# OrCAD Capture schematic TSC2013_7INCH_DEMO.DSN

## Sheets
1 BlockDiagram: size A3; rev: B
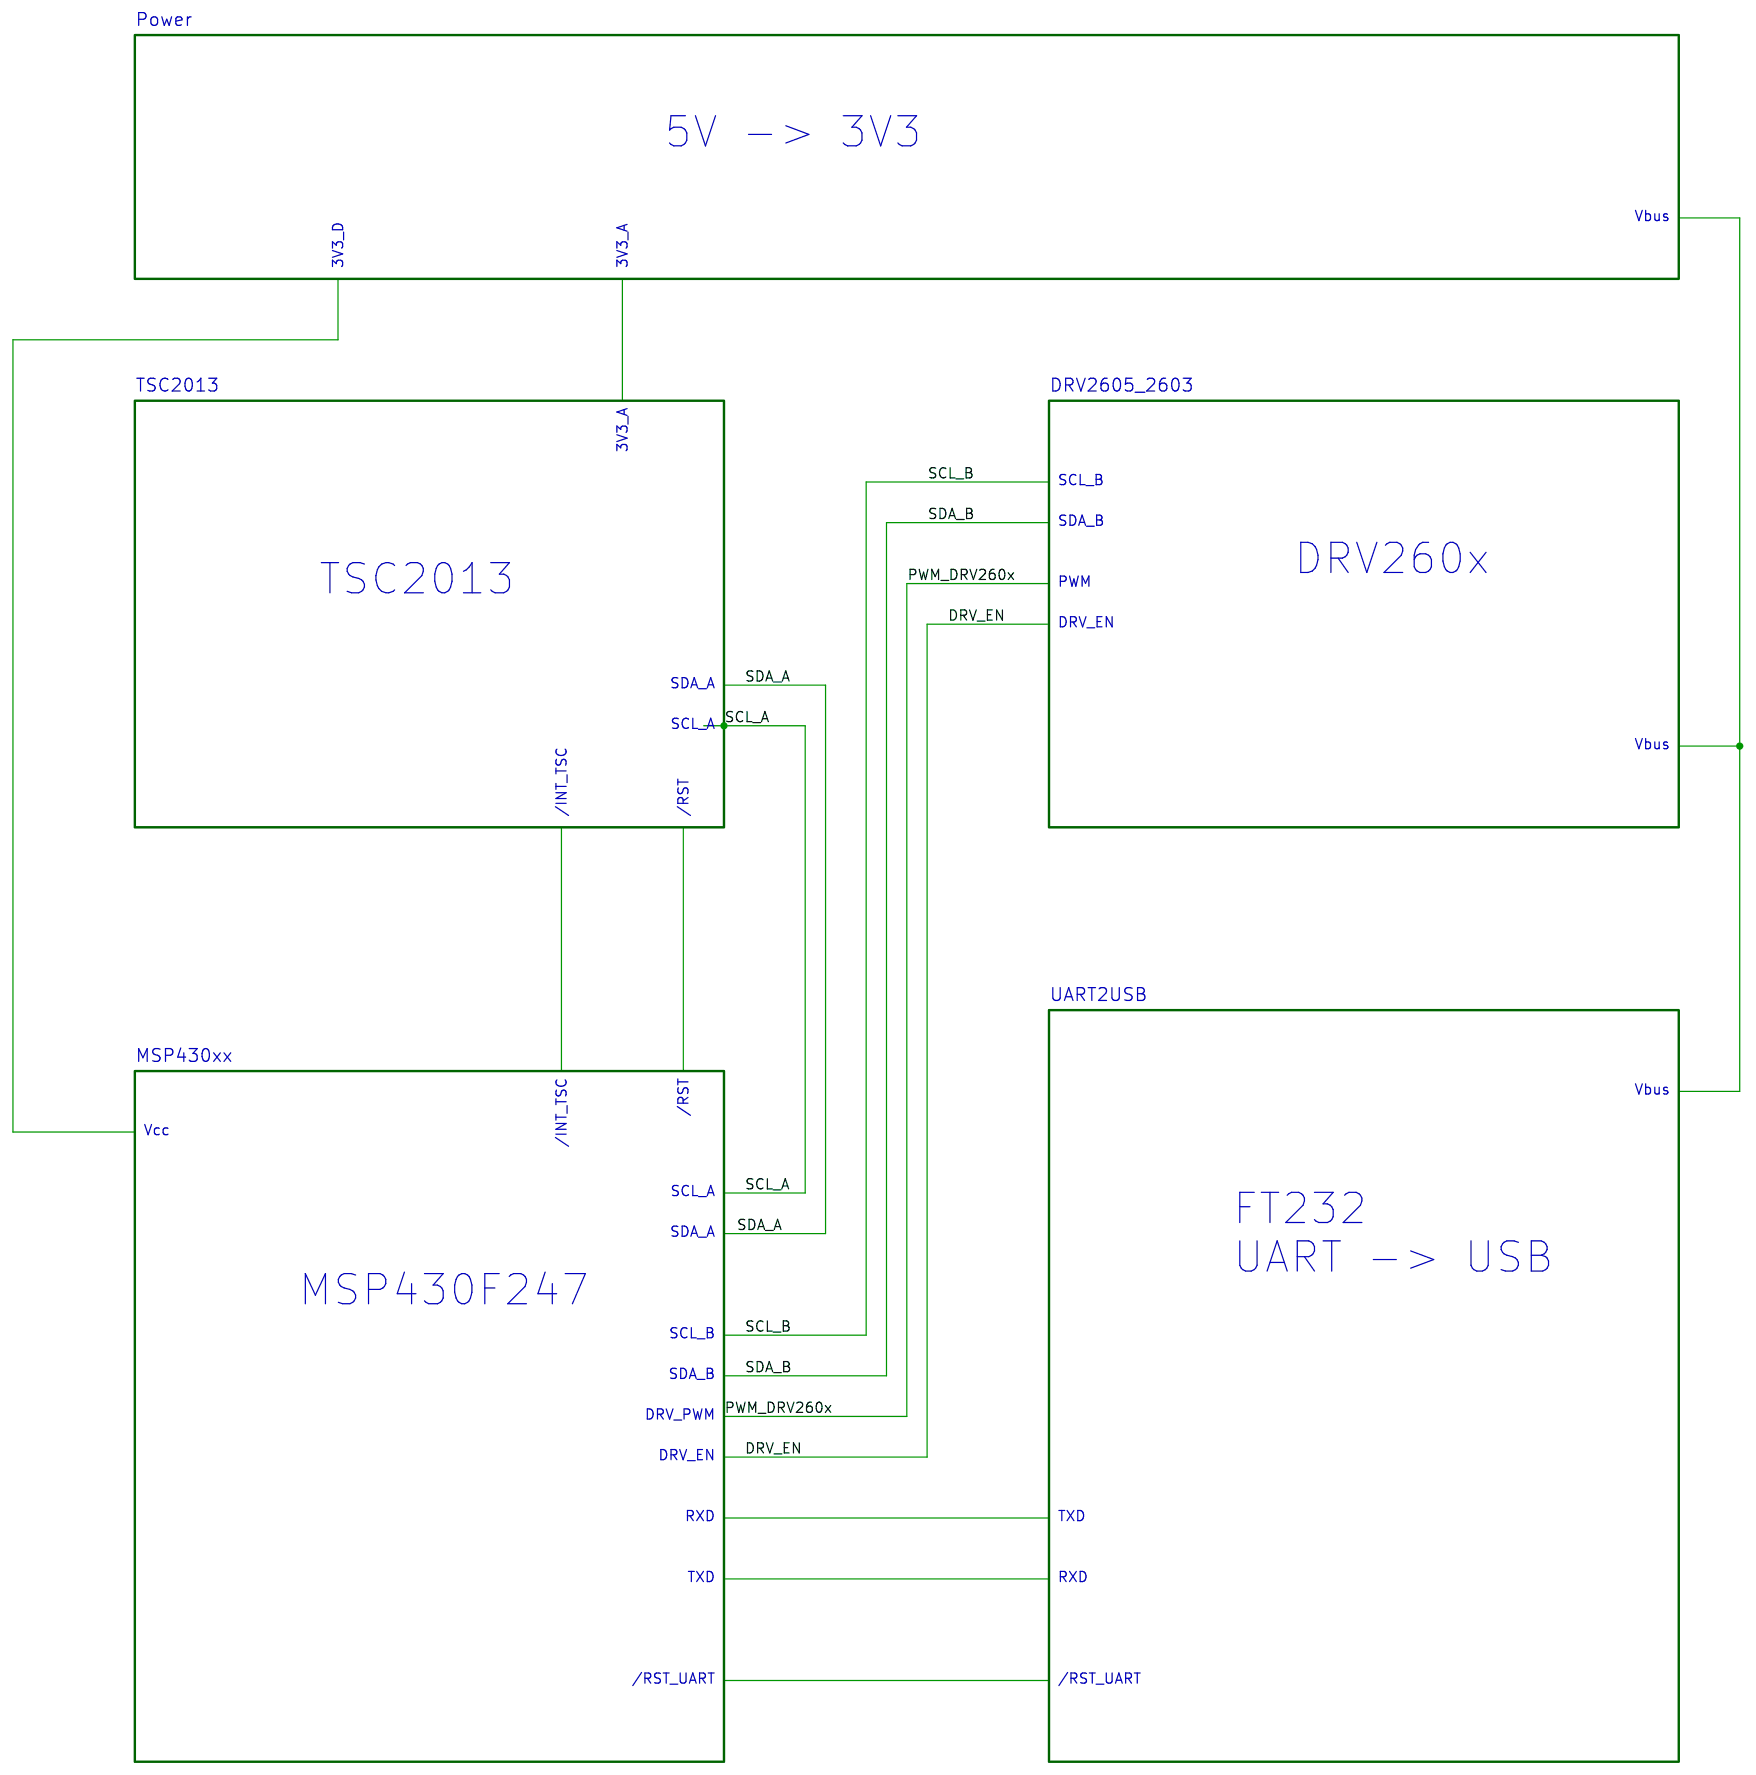
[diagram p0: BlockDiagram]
2 TSC2013: size A3; block TSC2013
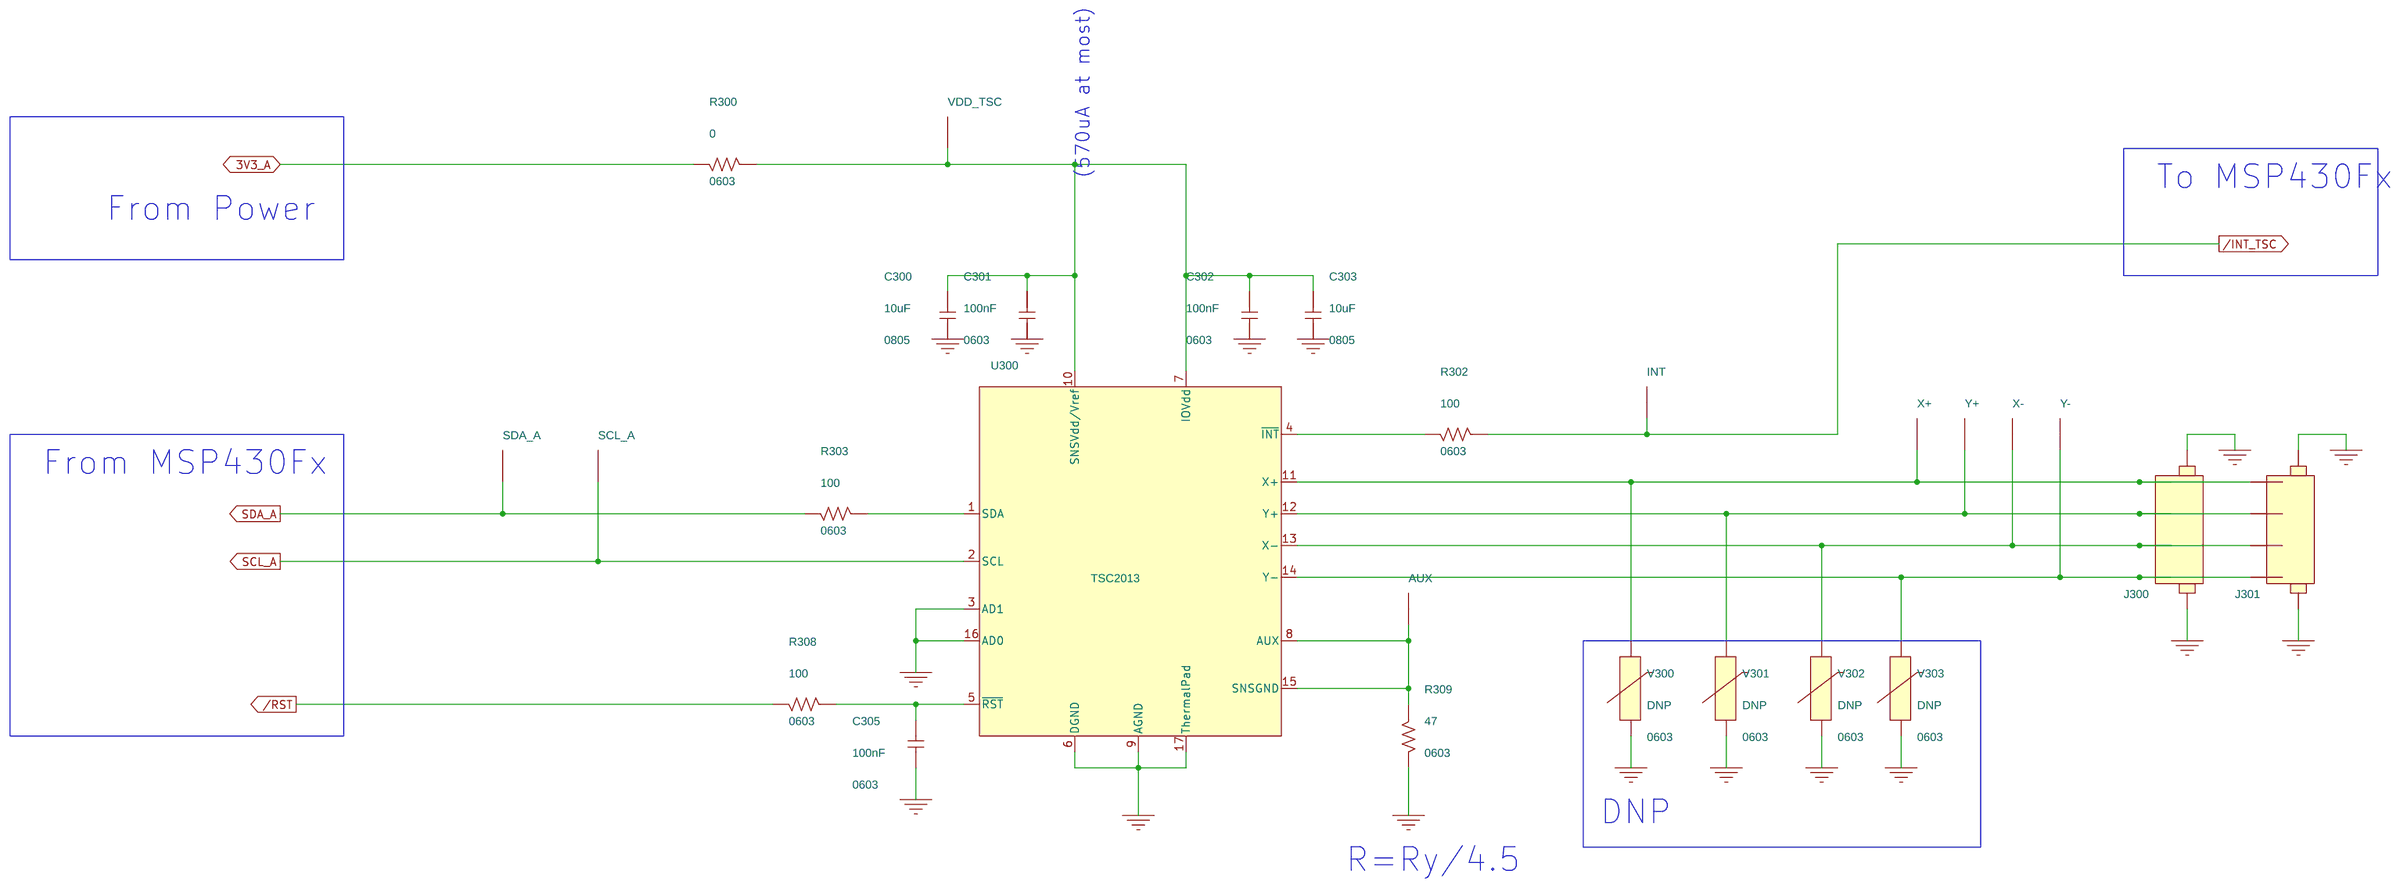
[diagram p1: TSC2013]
3 MSP430xx: size A3; block MSP430xx
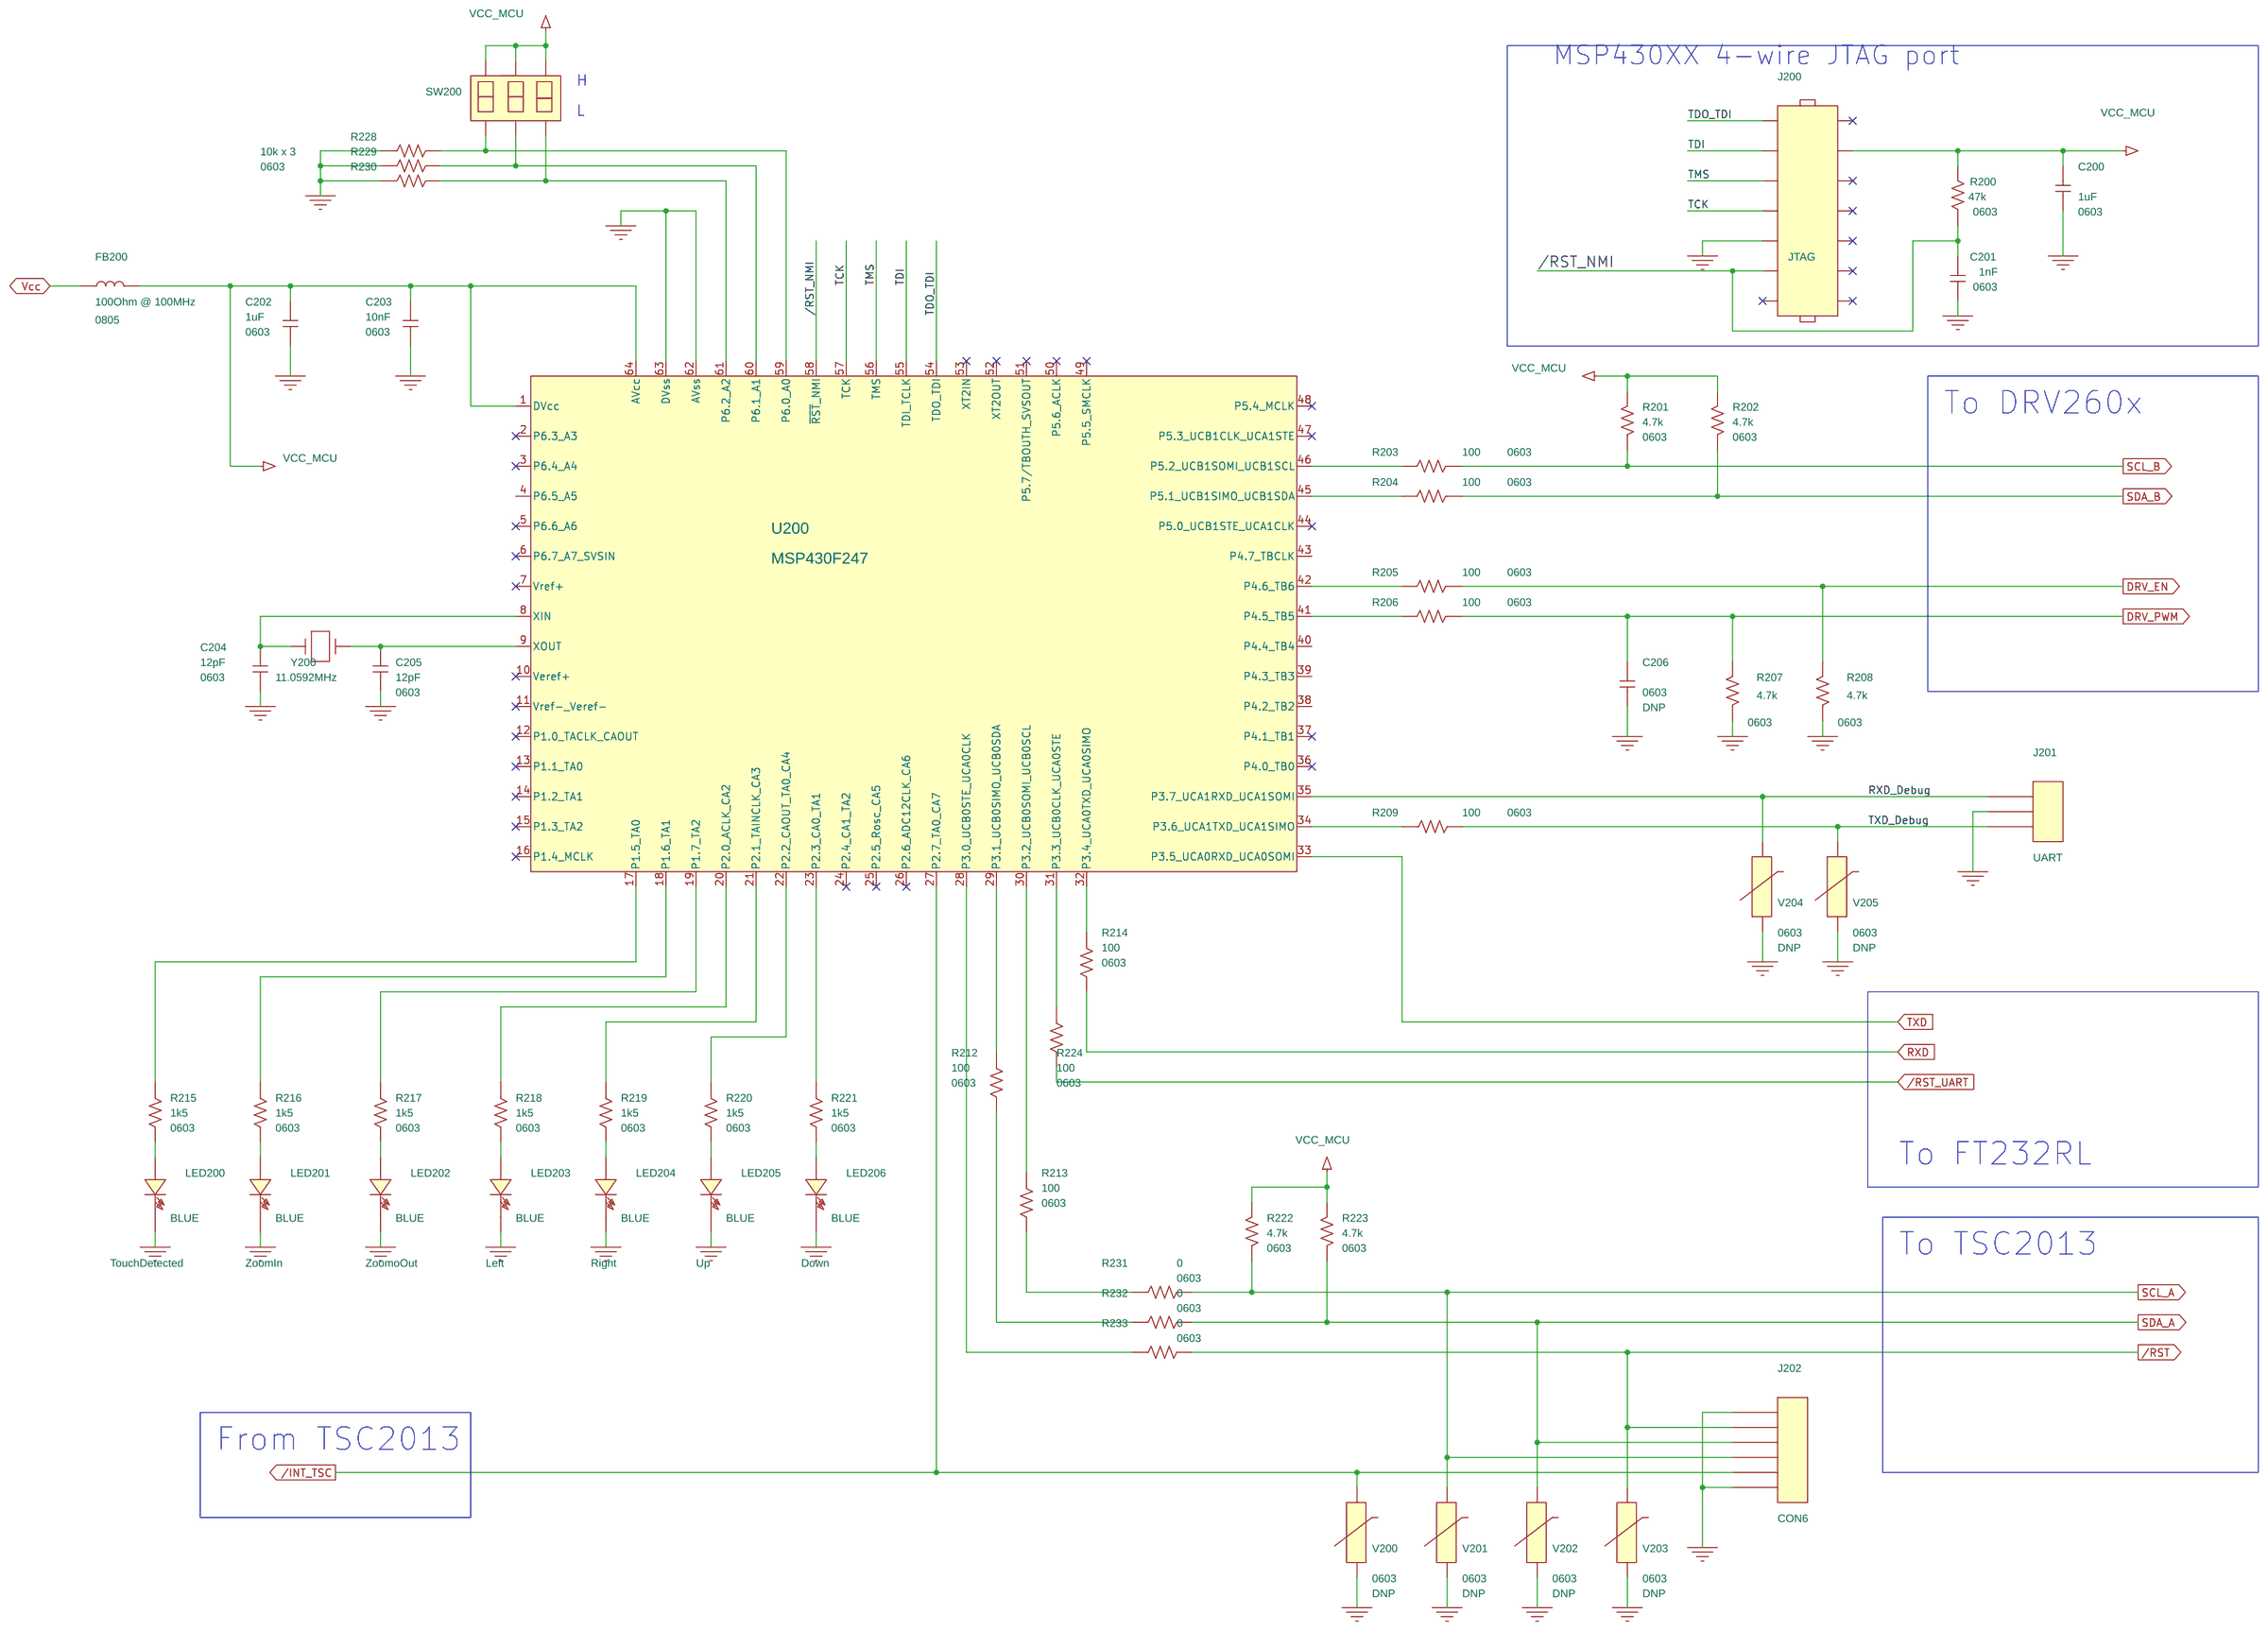
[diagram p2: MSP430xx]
4 DRV2605: size A3; block DRV2605_2603
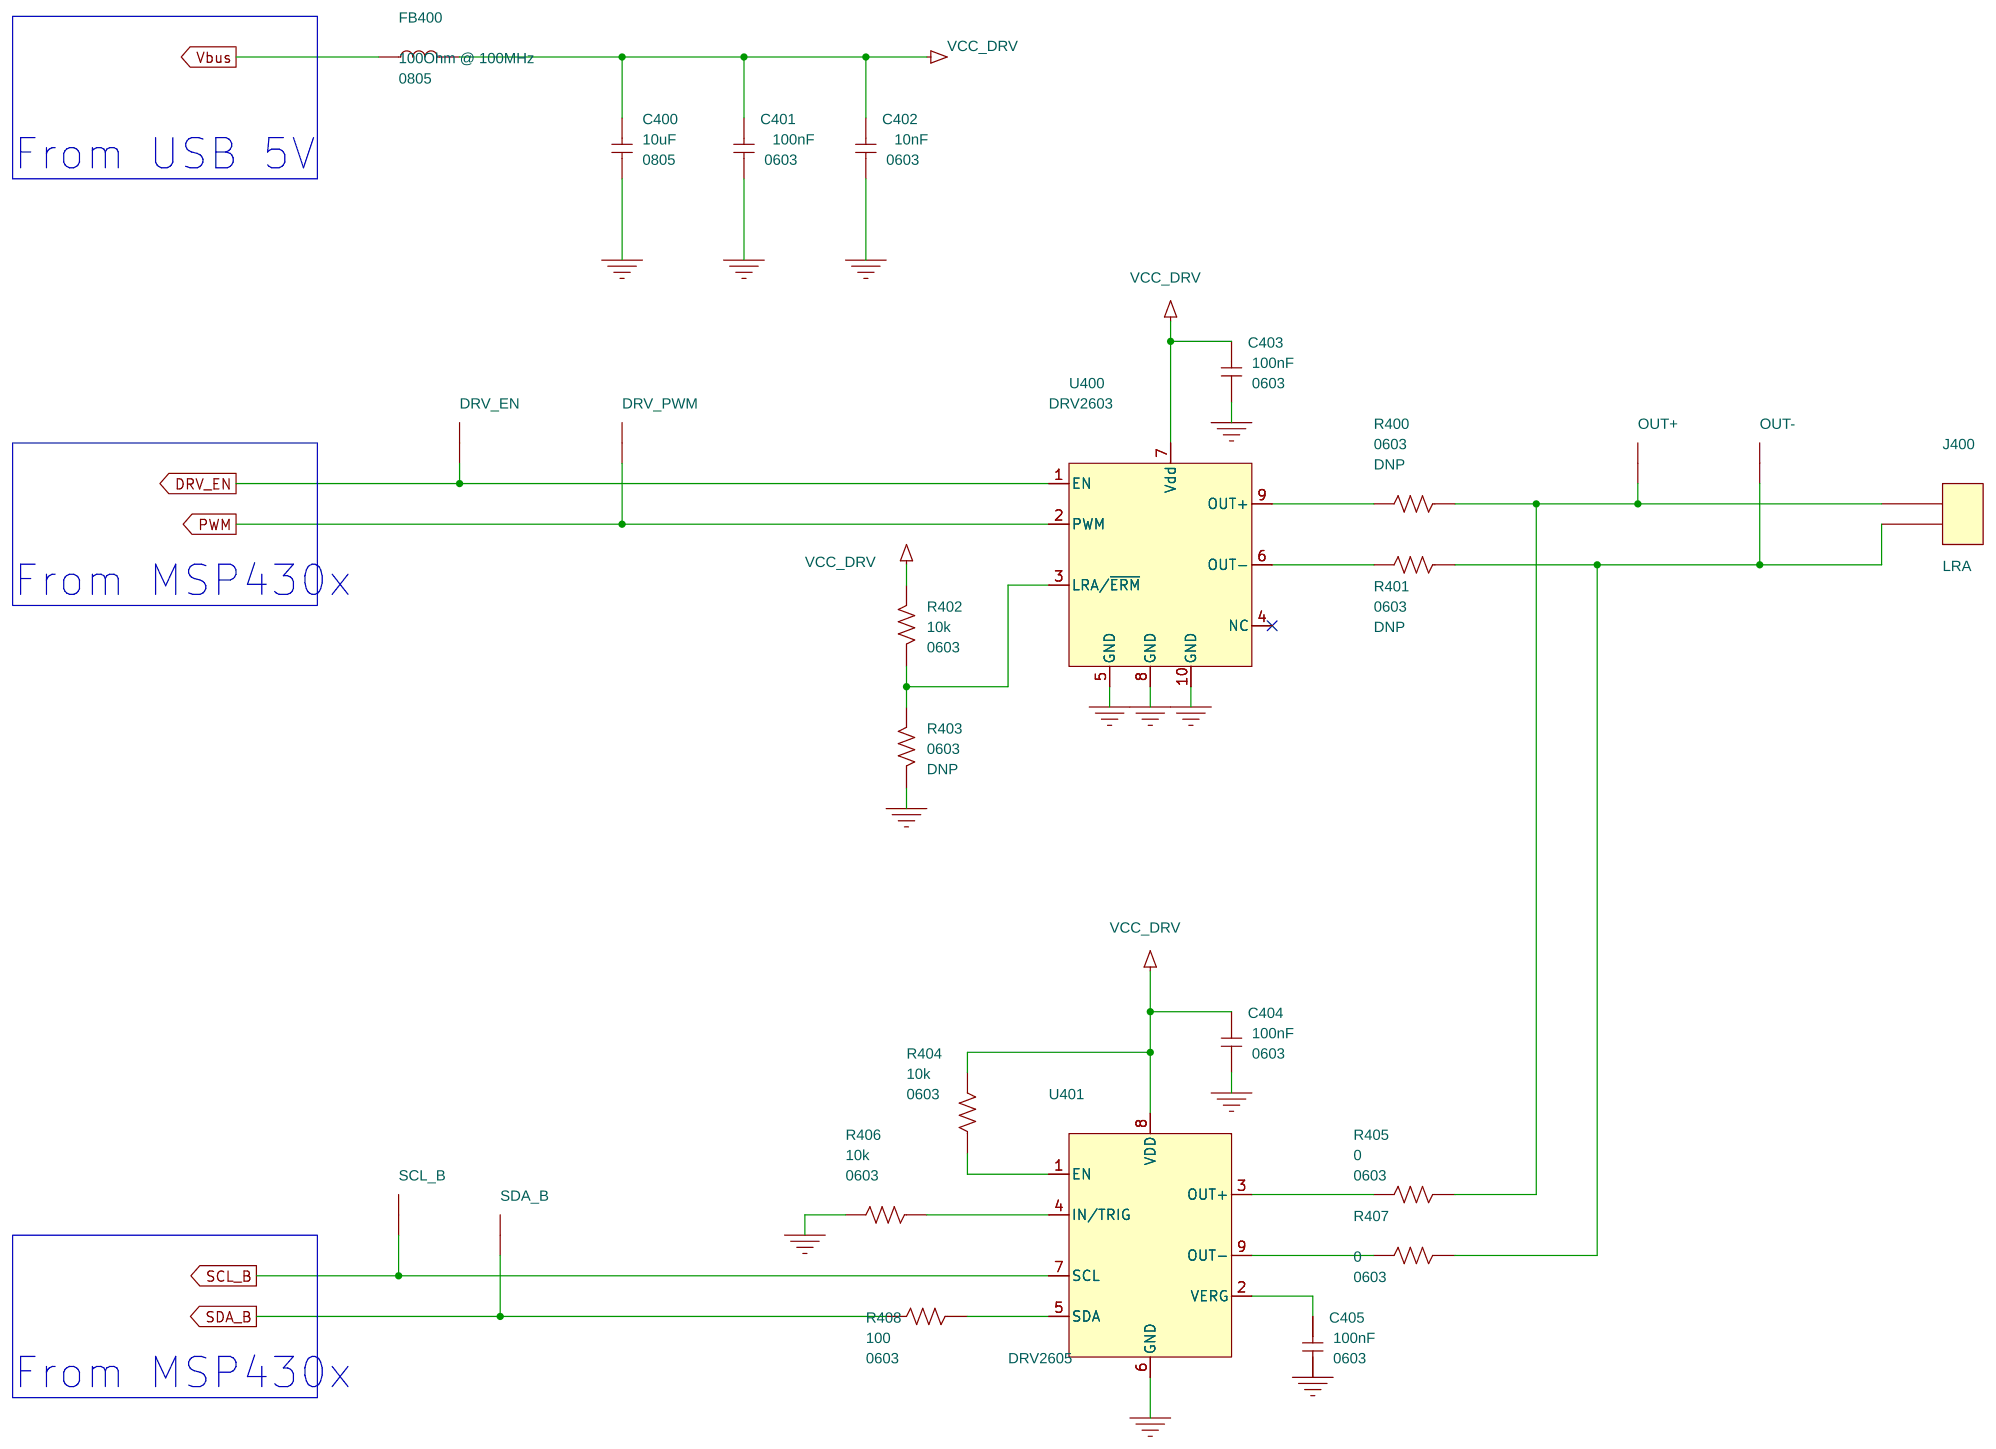
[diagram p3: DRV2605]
5 Power: size A3; block Power
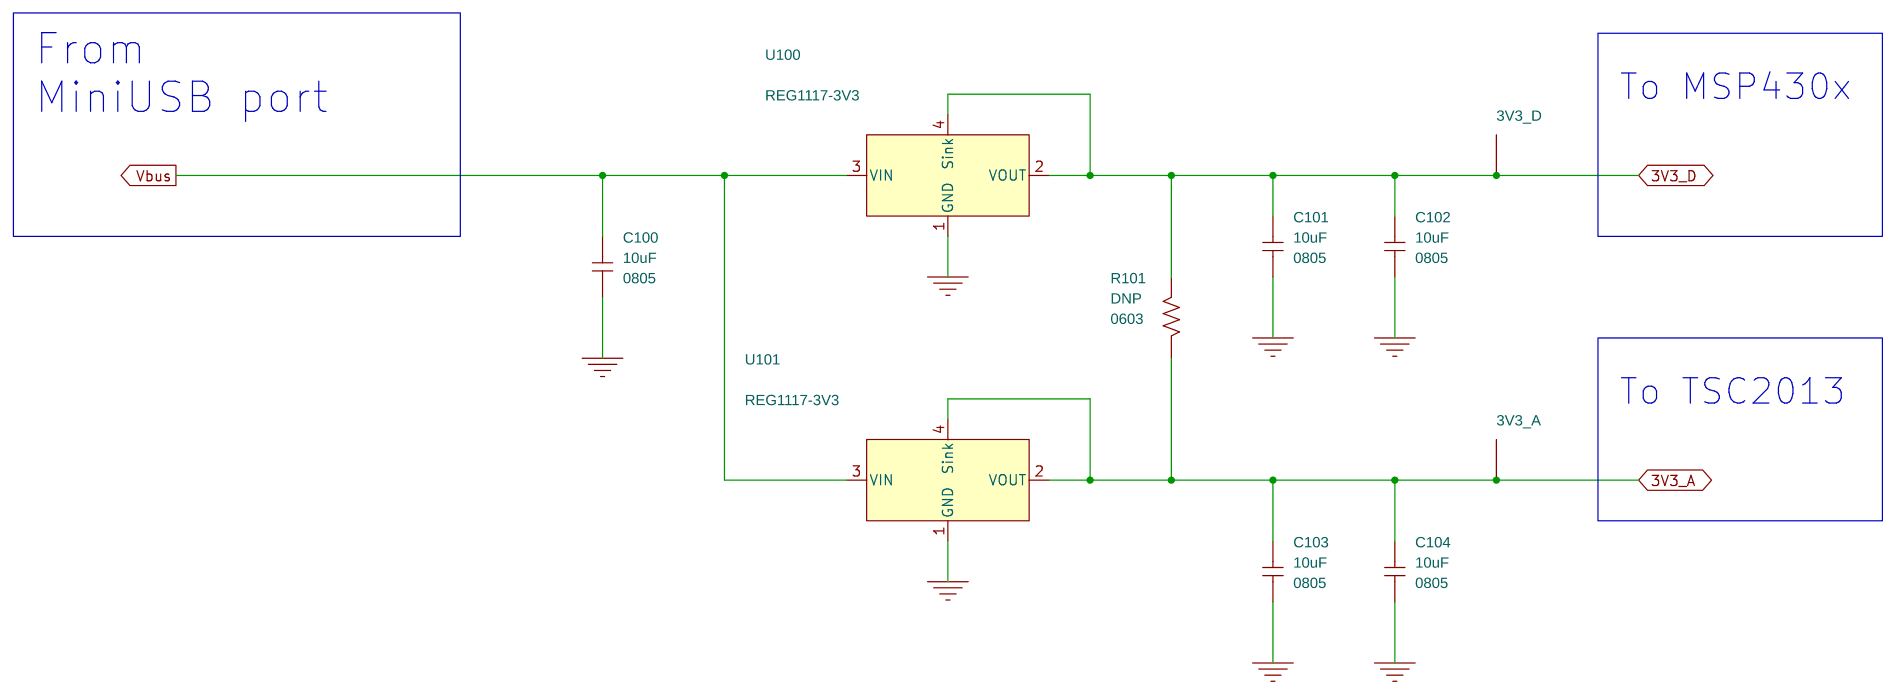
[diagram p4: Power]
6 UART2USB: size A3; block UART2USB
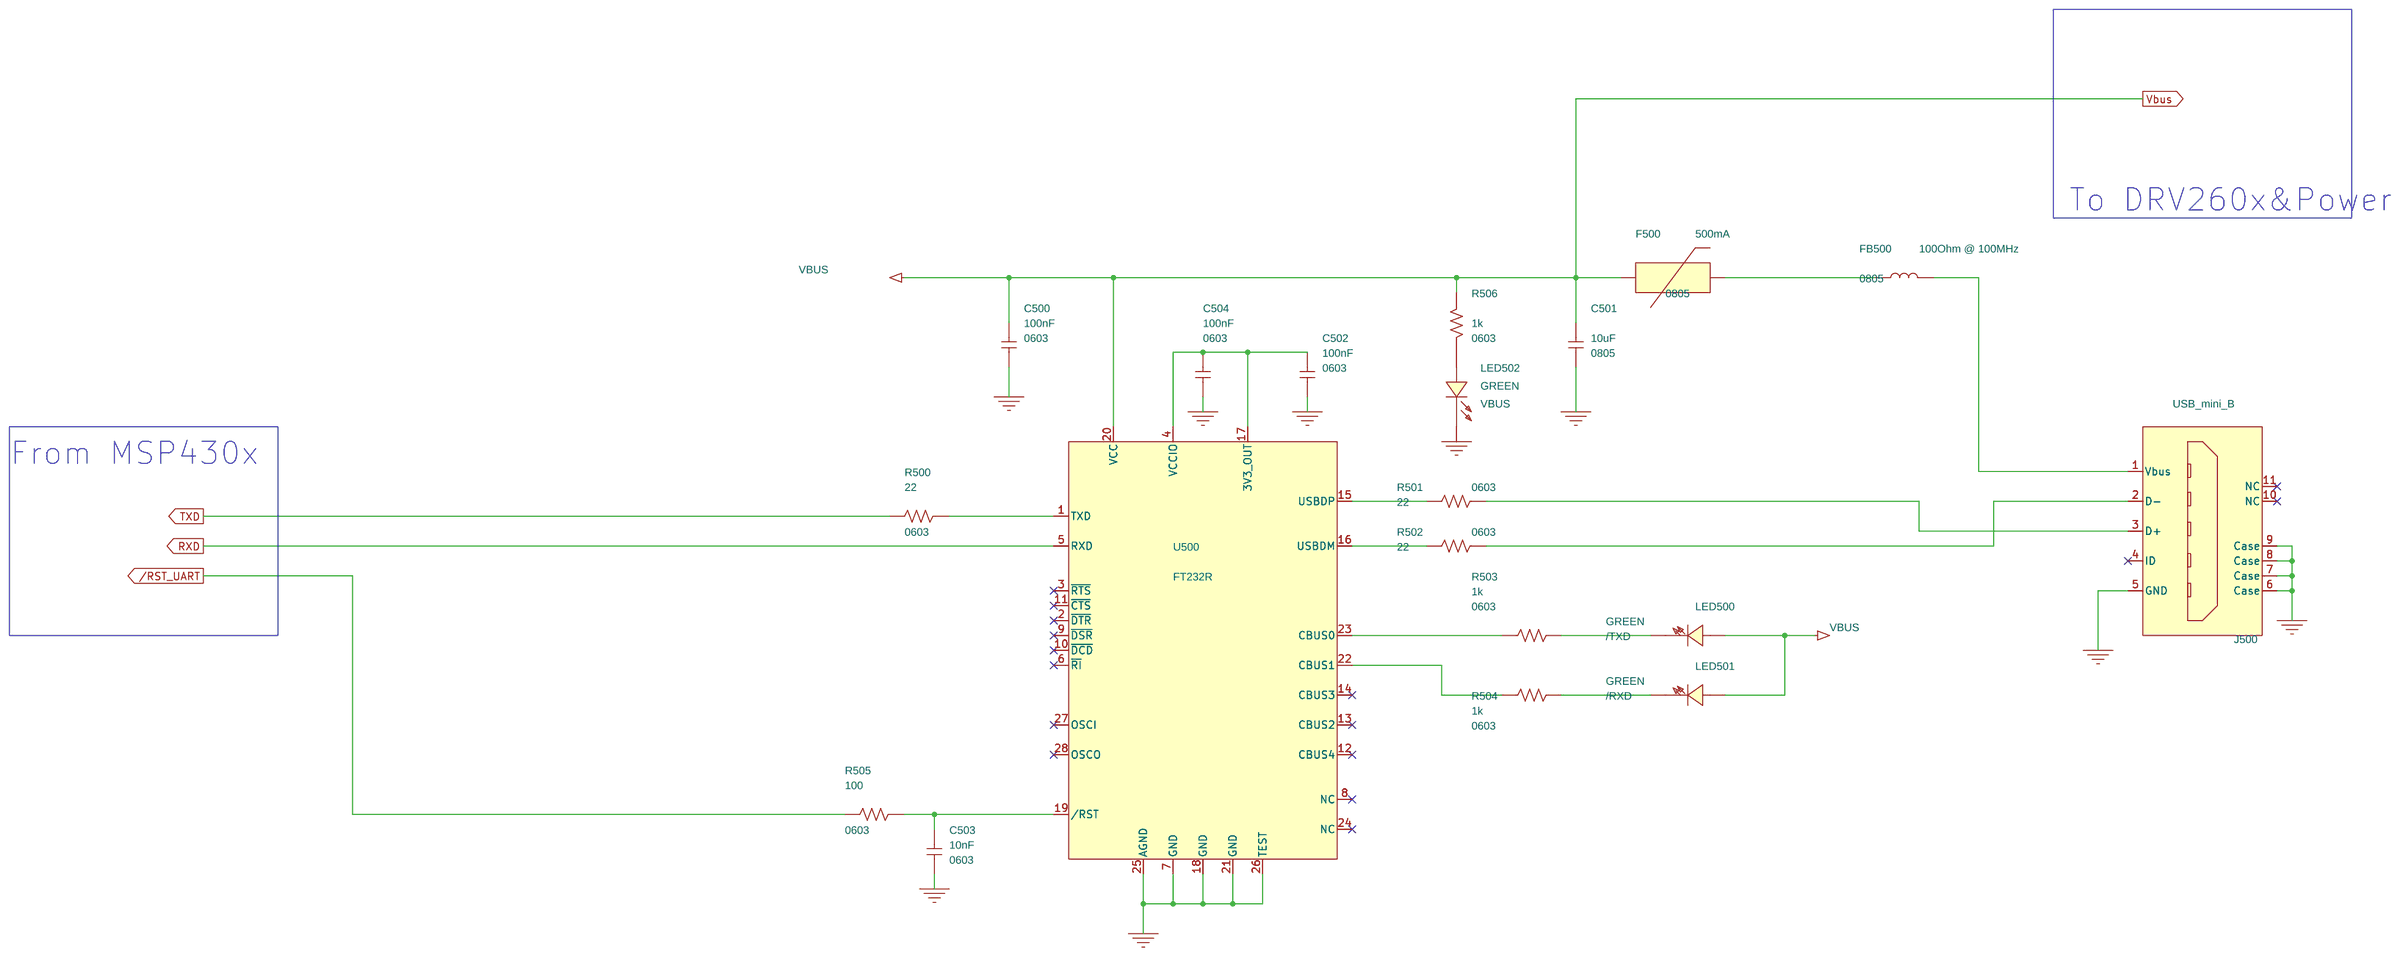
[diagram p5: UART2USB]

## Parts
sheet DRV2605
C400  10uF  [0805]
C401  100nF  [0603]
C402  10nF  [0603]
C403  100nF  [0603]
C404  100nF  [0603]
C405  100nF  [0603]
DRV_EN  TP  [TP_PAN]
DRV_PWM  TP  [TP_PAN]
FB400  100Ohm @ 100MHz  [0805]
J400  LRA  [LRA_ERM]
OUT+  TP  [TP_PAN]
OUT-  TP  [TP_PAN]
R400  0  [0603]
R401  0  [0603]
R402  10k  [0603]
R403  10k  [0603]
R404  10k  [0603]
R405  0  [0603]
R406  10k  [0603]
R407  0  [0603]
R408  100  [0603]
SCL_B  TP  [TP_PAN]
SDA_B  TP  [TP_PAN]
U400  DRV2603  [QFN50P200X200-10L]
U401  DRV2605  [BGA9P50]
sheet MSP430xx
C200  1uF  [0603]
C201  1nF  [0603]
C202  1uF  [0603]
C203  10nF  [0603]
C204  12pF  [0603]
C205  12pF  [0603]
C206  10nF  [0603]
FB200  100Ohm @ 100MHz  [0805]
J200  JTAG  [CON-HEADER14-POL_PAN]
J201  UART  [CON-SIP-3P_PAN]
J202  CON6  [CON-SIP-6P_PAN]
LED200  BLUE  [LED-0805_PAN]
LED201  BLUE  [LED-0805_PAN]
LED202  BLUE  [LED-0805_PAN]
LED203  BLUE  [LED-0805_PAN]
LED204  BLUE  [LED-0805_PAN]
LED205  BLUE  [LED-0805_PAN]
LED206  BLUE  [LED-0805_PAN]
R200  47k  [0603]
R201  4.7k  [0603]
R202  4.7k  [0603]
R203  100  [0603]
R204  100  [0603]
R205  100  [0603]
R206  100  [0603]
R207  4.7k  [0603]
R208  4.7k  [0603]
R209  100  [0603]
R212  100  [0603]
R213  100  [0603]
R214  100  [0603]
R215  1k5  [0603]
R216  1k5  [0603]
R217  1k5  [0603]
R218  1k5  [0603]
R219  1k5  [0603]
R220  1k5  [0603]
R221  1k5  [0603]
R222  4.7k  [0603]
R223  4.7k  [0603]
R224  100  [0603]
R228  10k  [0603]
R229  10k  [0603]
R230  10k x 3  [0603]
R231  0  [0603]
R232  0  [0603]
R233  0  [0603]
SW200  Switch  [SOP6_100milPitch]
U200  MSP430F247  [IC-QFP64-1200X1200_PAN]
V200  Varister  [0603]
V201  Varister  [0603]
V202  Varister  [0603]
V203  Varister  [0603]
V204  Varister  [0603]
V205  Varister  [0603]
Y200  11.0592MHz  [XT-SMT1140X480_PAN]
sheet Power
3V3_A  TP  [TP_PAN]
3V3_D  TP  [TP_PAN]
C100  10uF  [0805]
C101  10uF  [0805]
C102  10uF  [0805]
C103  10uF  [0805]
C104  10uF  [0805]
R101  0  [0603]
U100  REG1117-3V3  [SOT223]
U101  REG1117-3V3  [SOT223]
sheet TSC2013
AUX  TP  [TP_PAN]
C300  10uF  [0805]
C301  100nF  [0603]
C302  100nF  [0603]
C303  10uF  [0805]
C305  100nF  [0603]
INT  TP  [TP_PAN]
J300  CON6  [CON-SMT6-P1mm]
J301  CON6  [CON-SMT6-P1mm]
R300  0  [0603]
R302  100  [0603]
R303  100  [0603]
R308  100  [0603]
R309  47  [0603]
SCL_A  TP  [TP_PAN]
SDA_A  TP  [TP_PAN]
U300  TSC2013  [QFN65P400X400X100-17N_1]
V300  Varister  [0603]
V301  Varister  [0603]
V302  Varister  [0603]
V303  Varister  [0603]
VDD_TSC  TP  [TP_PAN]
X+  TP  [TP_PAN]
X-  TP  [TP_PAN]
Y+  TP  [TP_PAN]
Y-  TP  [TP_PAN]
sheet UART2USB
C500  100nF  [0603]
C501  10uF  [0805]
C502  100nF  [0603]
C503  10nF  [0603]
C504  100nF  [0603]
F500  500mA  [0805]
FB500  100Ohm @ 100MHz  [0805]
J500  USB_mini_B  [CON-USB_MINI]
LED500  GREEN  [LED-0805_PAN]
LED501  GREEN  [LED-0805_PAN]
LED502  GREEN  [LED-0805_PAN]
R500  22  [0603]
R501  22  [0603]
R502  22  [0603]
R503  1k  [0603]
R504  1k  [0603]
R505  100  [0603]
R506  1k  [0603]
U500  FT232R  [IC-TSSOP28-P65]

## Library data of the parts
C100-C104 C300 C303 C400 C501 = C
C201 C203 C301 C302 C305 C401-C405 C500 C502-C504 = C: VOLTAGE: 25V
3V3_A 3V3_D AUX DRV_EN DRV_PWM INT OUT+ OUT- SCL_A SCL_B SDA_A SDA_B VDD_TSC X+ X- Y+ Y- = TP
FB200 FB400 FB500 = FerriteBead
J400 = CON2
R400 R401 = R: Comments: DNP; PSpiceTemplate: R^@REFDES %1 %2 ?TOLERANCE|R^@REFDES| @VALUE TC=@TC1,@TC2 ?TOLERANCE|\n.model R^@REFDES RES R=1 DEV=@TOLERANCE% TC1=@TC1 TC2=@
R200-R209 R212-R224 R228-R233 R402 R404-R408 R500-R506 = R: PSpiceTemplate: R^@REFDES %1 %2 ?TOLERANCE|R^@REFDES| @VALUE TC=@TC1,@TC2 ?TOLERANCE|\n.model R^@REFDES RES R=1 DEV=@TOLERANCE% TC1=@TC1 TC2=@
R403 = R: PSpiceTemplate: R^@REFDES %1 %2 ?TOLERANCE|R^@REFDES| @VALUE TC=@TC1,@TC2 ?TOLERANCE|\n.model R^@REFDES RES R=1 DEV=@TOLERANCE% TC1=@TC1 TC2=@; comment: DNP
U400 = DRV2603_1
U401 = DRV2605
C200 C202 = C: VOLTAGE: 16V
C204 C205 = C: VOLTAGE: 50V
C206 = C: VOLTAGE: 25V; comment: DNP
J200 = CONN_PLUG_7x2_3
J201 = CON3
J202 = CON6
LED200 = LED_0: comment: TouchDetected
LED201 = LED_0: comment: ZoomIn
LED202 = LED_0: comment: ZoomoOut
LED203 = LED_0: comment: Left
LED204 = LED_0: comment: Right
LED205 = LED_0: comment: Up
LED206 = LED_0: comment: Down
SW200 = Switch_0
U200 = MSP430F247
V200-V205 = Varister: Comments: DNP
Y200 = ZTA
R101 = R: comment: DNP
U100 U101 = LT1117_1
J300 J301 = CON6_0
R300 R302 R303 R308 R309 = R
U300 = TSC2013_17
V300-V303 = Varister: comment: DNP
F500 = polyfuse
J500 = USB_mini_B
LED500 = LED_0: comment: /TXD
LED501 = LED_0: comment: /RXD
LED502 = LED_2: Comment: VBUS
U500 = FT232R

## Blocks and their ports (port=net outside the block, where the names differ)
TSC2013 = schematic TSC2013, on sheet BlockDiagram: 3V3_A=N00063, /RST=N01853, SCL_A, SDA_A, /INT_TSC=N01700
UART2USB = schematic UART2USB, on sheet BlockDiagram: Vbus=N02290, TXD=N02653, RXD=N02122, /RST_UART=N3636441
MSP430xx = schematic MSP430xx, on sheet BlockDiagram: Vcc=N00069, /RST=N01853, SCL_A, SDA_A, SCL_B, SDA_B, /INT_TSC=N01700, RXD=N02653, TXD=N02122, DRV_PWM=PWM_DRV260x, DRV_EN, /RST_UART=N3636441
Power = schematic Power, on sheet BlockDiagram: 3V3_D=N00069, 3V3_A=N00063, Vbus=N02290
DRV2605_2603 = schematic DRV26xx, on sheet BlockDiagram: Vbus=N02290, SDA_B, SCL_B, PWM=PWM_DRV260x, DRV_EN

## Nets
GND: C100.1 C101.1 C102.1 C103.1 C104.1 C200.1 C201.1 C202.1 C203.1 C204.2 C205.2 C206.1 C300.1 C301.1 C302.1 C303.1 C305.1 C400.1 C401.1 C402.1 C403.1 C404.1 C405.1 C500.1 C501.1 C502.1 C503.1 C504.1 J200.9 J201.2 J202.1 J202.6 J300.5 J300.6 J301.5 J301.6 J500.5(GND) J500.6(Case) J500.7(Case) J500.8(Case) J500.9(Case) LED200.2(CATHODE) LED201.2(CATHODE) LED202.2(CATHODE) LED203.2(CATHODE) LED204.2(CATHODE) LED205.2(CATHODE) LED206.2(CATHODE) LED502.2(CATHODE) R207.1 R208.1 R228.1 R229.1 R230.1 R309.2 R403.1 R406.2 U100.1(GND) U101.1(GND) U200.62(AVss) U200.63(DVss) U300.3(AD1) U300.6(DGND) U300.9(AGND) U300.16(AD0) U300.17(ThermalPad) U400.5(GND) U400.8(GND) U400.10(GND) U401.6(GND) U500.7(GND) U500.18(GND) U500.21(GND) U500.25(AGND) U500.26(TEST) V200.2 V201.2 V202.2 V203.2 V204.2 V205.2 V300.2 V301.2 V302.2 V303.2
Vcc_DRV: C400.2 C401.2 C402.2 C403.2 C404.2 FB400.1 R402.2 R404.2 U400.7(Vdd) U401.8(VDD)
Vcc_MCU: C200.2 C202.2 C203.2 FB200.1 J200.4 R200.2 R201.2 R202.2 R222.2 R223.2 SW200.4 SW200.5 SW200.6 U200.1(DVcc) U200.64(AVcc)
DRV_EN: DRV_EN.1(TP) R205.1 R208.2 U400.1(EN)
MSP430xx//RST_NMI: C201.2 J200.11 R200.1 U200.58(~{RST}_NMI)
MSP430xx/RXD_Debug: J201.1 U200.35(P3.7_UCA1RXD_UCA1SOMI) V204.1
MSP430xx/TCK: J200.7 U200.57(TCK)
MSP430xx/TDI: J200.3 U200.55(TDI_TCLK)
MSP430xx/TDO_TDI: J200.1 U200.54(TDO_TDI)
MSP430xx/TMS: J200.5 U200.56(TMS)
MSP430xx/TXD_Debug: J201.3 R209.2 V205.1
PWM_DRV260x: C206.2 DRV_PWM.1(TP) R206.1 R207.2 U400.2(PWM)
SCL_A: J202.4 R222.1 R231.2 SCL_A.1(TP) U300.2(SCL) V201.1
SCL_B: R201.1 R203.1 SCL_B.1(TP) U401.7(SCL)
SDA_A: J202.3 R223.1 R232.2 R303.2 SDA_A.1(TP) V202.1
SDA_B: R202.1 R204.1 R408.2 SDA_B.1(TP)
DRV2605_2603/N3637757: R402.1 R403.2 U400.3(LRA/~{ERM})
DRV2605_2603/N3638887: R400.2 U400.9(OUT+)
DRV2605_2603/N3638891: R401.2 U400.6(OUT-)
DRV2605_2603/N3639081: R404.1 U401.1(EN)
DRV2605_2603/N3639231: R406.1 U401.4(IN/TRIG)
DRV2605_2603/N3639367: R405.2 U401.3(OUT+)
DRV2605_2603/N3639371: R407.2 U401.9(OUT-)
DRV2605_2603/N3639383: J400.1 OUT+.1(TP) R400.1 R405.1
DRV2605_2603/N3639411: J400.2 OUT-.1(TP) R401.1 R407.1
DRV2605_2603/N3639450: C405.2 U401.2(VERG)
DRV2605_2603/N3639487: R408.1 U401.5(SDA)
MSP430xx/N242258: C205.1 U200.9(XOUT) Y200.2
MSP430xx/N242262: C204.1 U200.8(XIN) Y200.1
MSP430xx/N242746: R203.2 U200.46(P5.2_UCB1SOMI_UCB1SCL)
MSP430xx/N242808: R204.2 U200.45(P5.1_UCB1SIMO_UCB1SDA)
MSP430xx/N243076: R212.1 U200.29(P3.1_UCB0SIMO_UCB0SDA)
MSP430xx/N243096: R212.2 R232.1
MSP430xx/N243106: R213.1 U200.30(P3.2_UCB0SOMI_UCB0SCL)
MSP430xx/N243110: R213.2 R231.1
MSP430xx/N247962: R233.1 U200.28(P3.0_UCB0STE_UCA0CLK)
MSP430xx/N249094: LED200.1(ANODE) R215.2
MSP430xx/N249134: LED201.1(ANODE) R216.2
MSP430xx/N250091: R209.1 U200.34(P3.6_UCA1TXD_UCA1SIMO)
MSP430xx/N251308: LED202.1(ANODE) R217.2
MSP430xx/N251435: LED203.1(ANODE) R218.2
MSP430xx/N251541: LED204.1(ANODE) R219.2
MSP430xx/N251818: LED205.1(ANODE) R220.2
MSP430xx/N251860: LED206.1(ANODE) R221.2
MSP430xx/N252378: R205.2 U200.42(P4.6_TB6)
MSP430xx/N252382: R206.2 U200.41(P4.5_TB5)
MSP430xx/N252740: R215.1 U200.17(P1.5_TA0)
MSP430xx/N252751: R216.1 U200.18(P1.6_TA1)
MSP430xx/N252768: R217.1 U200.19(P1.7_TA2)
MSP430xx/N252775: R218.1 U200.20(P2.0_ACLK_CA2)
MSP430xx/N252782: R219.1 U200.21(P2.1_TAINCLK_CA3)
MSP430xx/N252797: R220.1 U200.22(P2.2_CAOUT_TA0_CA4)
MSP430xx/N3647650: R221.1 U200.23(P2.3_CA0_TA1)
MSP430xx/N3651457: R224.1 U200.31(P3.3_UCB0CLK_UCA0STE)
MSP430xx/N3656955: R214.1 U200.32(P3.4_UCA0TXD_UCA0SIMO)
MSP430xx/N3657119: R228.2 SW200.1 U200.59(P6.0_A0)
MSP430xx/N3657123: R229.2 SW200.2 U200.60(P6.1_A1)
MSP430xx/N3658263: R230.2 SW200.3 U200.61(P6.2_A2)
N00063: 3V3_A.1(TP) C103.2 C104.2 R101.1 R300.2 U101.2(VOUT) U101.4(Sink)
N00069: 3V3_D.1(TP) C101.2 C102.2 FB200.2 R101.2 U100.2(VOUT) U100.4(Sink)
N01700: INT.1(TP) J202.5 R302.1 U200.27(P2.7_TA0_CA7) V200.1
N01853: J202.2 R233.2 R308.2 V203.1
N02122: U200.33(P3.5_UCA0RXD_UCA0SOMI) U500.5(RXD)
N02290: C100.2 C500.2 C501.2 F500.1 FB400.2 LED500.1(ANODE) LED501.1(ANODE) R506.1 U100.3(VIN) U101.3(VIN) U500.20(VCC)
N02653: R214.2 R500.2
N3636441: R224.2 R505.2
N3655201: LED502.1(ANODE) R506.2
TSC2013/N3636152: C300.2 C301.2 C302.2 C303.2 R300.1 U300.7(IOVdd) U300.10(SNSVdd/Vref) VDD_TSC.1(TP)
TSC2013/N3637453: C305.2 R308.1 U300.5(~{RST})
TSC2013/N3637710: R303.1 U300.1(SDA)
TSC2013/N3637792: AUX.1(TP) R309.1 U300.8(AUX) U300.15(SNSGND)
TSC2013/N3637846: R302.2 U300.4(~{INT})
TSC2013/N3638094: J300.4 J301.4 U300.11(X+) V300.1 X+.1(TP)
TSC2013/N3638098: J300.3 J301.3 U300.12(Y+) V301.1 Y+.1(TP)
TSC2013/N3638102: J300.2 J301.2 U300.13(X-) V302.1 X-.1(TP)
TSC2013/N3638106: J300.1 J301.1 U300.14(Y-) V303.1 Y-.1(TP)
UART2USB/N00206: J500.3(D+) R501.1
UART2USB/N00258: FB500.1 J500.1(Vbus)
UART2USB/N00357: J500.2(D-) R502.1
UART2USB/N3639567: R501.2 U500.15(USBDP)
UART2USB/N3639595: R502.2 U500.16(USBDM)
UART2USB/N3640580: R504.1 U500.22(CBUS1)
UART2USB/N3640948: R500.1 U500.1(TXD)
UART2USB/N3641556: C503.2 R505.1 U500.19(/RST)
UART2USB/N3641870: C502.2 C504.2 U500.4(VCCIO) U500.17(3V3_OUT)
UART2USB/N3642749: F500.2 FB500.2
UART2USB/N3645146: LED500.2(CATHODE) R503.2
UART2USB/N3645150: LED501.2(CATHODE) R504.2
UART2USB/N3645191: R503.1 U500.23(CBUS0)

Not connected (* = marked no-connect by the designer): J200 2* 6* 8* 10* 12* 13* 14*; J500 4(ID)* 10(NC)* 11(NC)*; U200 2(P6.3_A3)* 3(P6.4_A4)* 4(P6.5_A5) 5(P6.6_A6)* 6(P6.7_A7_SVSIN)* 7(Vref+)* 10(Veref+)* 11(Vref-_Veref-)* 12(P1.0_TACLK_CAOUT)* 13(P1.1_TA0)* 14(P1.2_TA1)* 15(P1.3_TA2)* 16(P1.4_MCLK)* 24(P2.4_CA1_TA2)* 25(P2.5_Rosc_CA5)* 26(P2.6_ADC12CLK_CA6)* 36(P4.0_TB0)* 37(P4.1_TB1)* 38(P4.2_TB2) 39(P4.3_TB3) 40(P4.4_TB4) 43(P4.7_TBCLK) 44(P5.0_UCB1STE_UCA1CLK)* 47(P5.3_UCB1CLK_UCA1STE)* 48(P5.4_MCLK)* 49(P5.5_SMCLK)* 50(P5.6_ACLK)* 51(P5.7/TBOUTH_SVSOUT)* 52(XT2OUT)* 53(XT2IN)*; U400 4(NC)*; U500 2(~{DTR})* 3(~{RTS})* 6(~{RI})* 8(NC)* 9(~{DSR})* 10(~{DCD})* 11(~{CTS})* 12(CBUS4)* 13(CBUS2)* 14(CBUS3)* 24(NC)* 27(OSCI)* 28(OSCO)*

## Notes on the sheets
sheet 1
- 5V -> 3V3
- TSC2013
- DRV260x
- FT232
  UART -> USB
- MSP430F247
sheet 2
- To MSP430Fx
- (570uA at most)
- From Power
- From MSP430Fx
- DNP
- R=Ry/4.5
sheet 3
- MSP430XX 4-wire JTAG port
- H
- L
- To DRV260x
- To FT232RL
- To TSC2013
- From TSC2013
sheet 4
- From USB 5V
- From MSP430x
- From MSP430x
sheet 5
- From
  MiniUSB port
- To MSP430x
- To TSC2013
sheet 6
- To DRV260x&Power
- From MSP430x
